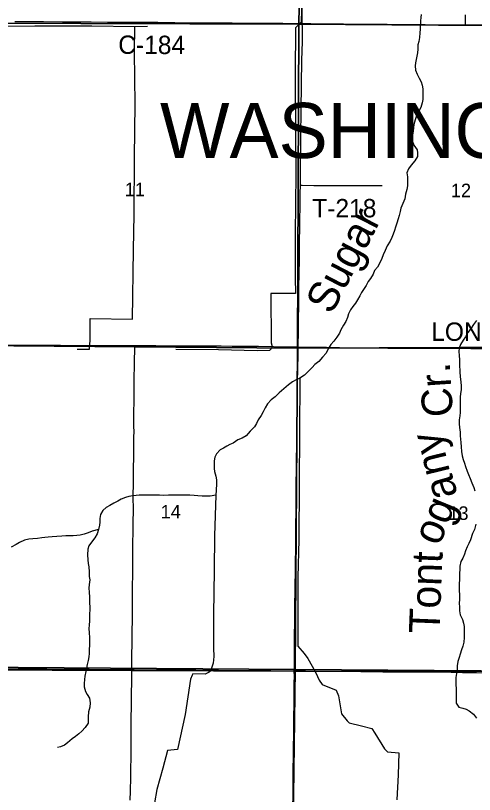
# Model space of a CAD drawing. Extents: x 1443599 to 1910620, y 1028088 to 1361369.
# Drawn here: x 1610745 to 1618246, y 1234297 to 1247021 of the extents above; entities that cross this region are included whole.
import ezdxf

# ---------------------------------------------------------------- set-up
doc = ezdxf.new("R2010")
doc.units = 0
for name, color, linetype in [('GM_X_County_Road', 7, 'Continuous'), ('GM_X_County_Road_Text', 7, 'Continuous'), ('GM_X_Minor_River', 7, 'Continuous'), ('GM_X_Minor_River_Text', 7, 'Continuous'), ('GM_X_Section', 7, 'Continuous'), ('GM_X_Section_Text', 7, 'Continuous'), ('GM_X_State_Route', 7, 'Continuous'), ('GM_X_Township', 7, 'Continuous'), ('GM_X_Township_Road', 7, 'Continuous'), ('GM_X_Township_Road_Text', 7, 'Continuous'), ('GM_X_Township_Text', 7, 'Continuous')]:
    doc.layers.add(name, color=color, linetype=linetype)

msp = doc.modelspace()

# ---------------------------------------------------------------- linework, layer by layer
at = {"layer": 'GM_X_County_Road'}
for points in [[(1610731, 1246926), (1610938, 1246925), (1611099, 1246924), (1611204, 1246924), (1611513, 1246920), (1611703, 1246920), (1611805, 1246919), (1611982, 1246918), (1612248, 1246916), (1612543, 1246914), (1612688, 1246913), (1612954, 1246912), (1613069, 1246911), (1613348, 1246909), (1613942, 1246904), (1614283, 1246902), (1614513, 1246900), (1614723, 1246898), (1614956, 1246896), (1615116, 1246895), (1615304, 1246893), (1615427, 1246892), (1615432, 1246891)], [(1615432, 1246891), (1615570, 1246890), (1615783, 1246887), (1615928, 1246886), (1616105, 1246884), (1616299, 1246883), (1616561, 1246882), (1616686, 1246881), (1616817, 1246880), (1617034, 1246877), (1617175, 1246875), (1617257, 1246875), (1617441, 1246873), (1617608, 1246871), (1617766, 1246870), (1617927, 1246869), (1618084, 1246870), (1618098, 1246869)], [(1618098, 1246869), (1618291, 1246869), (1618596, 1246868), (1618843, 1246867), (1618951, 1246866), (1619036, 1246866), (1619145, 1246866), (1619230, 1246866), (1619338, 1246865), (1619393, 1246865), (1619473, 1246865), (1619614, 1246864), (1619834, 1246863), (1619913, 1246863), (1620001, 1246863), (1620110, 1246862), (1620225, 1246861), (1620389, 1246860), (1620513, 1246859), (1620589, 1246859), (1620665, 1246859), (1620750, 1246859), (1620771, 1246859)]]:
    msp.add_lwpolyline(points, dxfattribs=at)
at = {"layer": 'GM_X_Minor_River'}
for points in [[(1615422, 1247329), (1615413, 1246916), (1615323, 1246819), (1615316, 1246074), (1615319, 1245088), (1615327, 1244437), (1615316, 1243457), (1615318, 1242736), (1615321, 1242483), (1614920, 1242479), (1614923, 1241672), (1614939, 1241615), (1614923, 1241574), (1614894, 1241549), (1614694, 1241546), (1614061, 1241561), (1613365, 1241567)], [(1617375, 1247038), (1617371, 1246988), (1617363, 1246934), (1617358, 1246800), (1617352, 1246740), (1617349, 1246665), (1617337, 1246598), (1617323, 1246544), (1617320, 1246472), (1617314, 1246410), (1617306, 1246356), (1617294, 1246302), (1617282, 1246250), (1617276, 1246198), (1617284, 1246130), (1617308, 1246062), (1617343, 1245997), (1617377, 1245939), (1617393, 1245887), (1617401, 1245824), (1617401, 1245774), (1617403, 1245713), (1617401, 1245649), (1617393, 1245597), (1617370, 1245522), (1617331, 1245447), (1617301, 1245382), (1617279, 1245318), (1617256, 1245243), (1617250, 1245189), (1617244, 1245131)], [(1612901, 1246843), (1612692, 1246837), (1611992, 1246847), (1611059, 1246846), (1609988, 1246840)], [(1611752, 1241572), (1611953, 1241572), (1611964, 1241718), (1611965, 1241979), (1611963, 1242074), (1612654, 1242060), (1612675, 1243194), (1612686, 1243774), (1612687, 1244706), (1612699, 1245573), (1612691, 1246423), (1612692, 1246837)], [(1617244, 1245131), (1617236, 1245069), (1617236, 1245013), (1617236, 1244962), (1617254, 1244906), (1617309, 1244827), (1617317, 1244777), (1617315, 1244717), (1617271, 1244648), (1617212, 1244580), (1617166, 1244517), (1617143, 1244452), (1617153, 1244387), (1617152, 1244311), (1617152, 1244241), (1617141, 1244181), (1617121, 1244103), (1617108, 1244027), (1617042, 1243873), (1617032, 1243821), (1617016, 1243756), (1617000, 1243700), (1616977, 1243628), (1616957, 1243563), (1616939, 1243509), (1616917, 1243448), (1616895, 1243395), (1616866, 1243337), (1616821, 1243259), (1616787, 1243182), (1616754, 1243111), (1616730, 1243053), (1616697, 1242984), (1616659, 1242911), (1616612, 1242855), (1616588, 1242799), (1616546, 1242727), (1616510, 1242674), (1616475, 1242611), (1616435, 1242546), (1616401, 1242495), (1616371, 1242444), (1616332, 1242377), (1616300, 1242322), (1616260, 1242267), (1616220, 1242214), (1616188, 1242149), (1616170, 1242088), (1616143, 1242023), (1616105, 1241964), (1616062, 1241887), (1616042, 1241833), (1615999, 1241765), (1615945, 1241700), (1615901, 1241648), (1615854, 1241575), (1615824, 1241508), (1615761, 1241438), (1615700, 1241370), (1615638, 1241320), (1615595, 1241270), (1615534, 1241210), (1615466, 1241148), (1615390, 1241096), (1615331, 1241072), (1615273, 1241040), (1615209, 1240989), (1615131, 1240921), (1615056, 1240856), (1614986, 1240794), (1614922, 1240742), (1614865, 1240676), (1614827, 1240611), (1614792, 1240548), (1614760, 1240485), (1614709, 1240415), (1614683, 1240357), (1614651, 1240300), (1614582, 1240229), (1614515, 1240155), (1614450, 1240119), (1614379, 1240092), (1614301, 1240038), (1614250, 1240014), (1614198, 1239986), (1614143, 1239956), (1614092, 1239927), (1614027, 1239860), (1614001, 1239804), (1613991, 1239746), (1613989, 1239694), (1613991, 1239622), (1613997, 1239572), (1614016, 1239494), (1614028, 1239436), (1614030, 1239369), (1614022, 1239265)], [(1618280, 1242038), (1618233, 1241976), (1618191, 1241917), (1618140, 1241841), (1618098, 1241772), (1618062, 1241719), (1618019, 1241648), (1617995, 1241585), (1617993, 1241535), (1617995, 1241466), (1618000, 1241396), (1618002, 1241328), (1618005, 1241195), (1618010, 1241124), (1618025, 1241031), (1618031, 1240971), (1618029, 1240909), (1618018, 1240849), (1618014, 1240787), (1618012, 1240717), (1618013, 1240650), (1618013, 1240600), (1618011, 1240534), (1618007, 1240484), (1617997, 1240416), (1617994, 1240350), (1618002, 1240289), (1618010, 1240215), (1618013, 1240154), (1618020, 1240100), (1618024, 1240048), (1618027, 1239973), (1618032, 1239897), (1618044, 1239826), (1618064, 1239771), (1618086, 1239708), (1618102, 1239653), (1618129, 1239578), (1618151, 1239523), (1618175, 1239456), (1618204, 1239386), (1618238, 1239311), (1618252, 1239258)], [(1615390, 1241096), (1615384, 1240205), (1615382, 1239376), (1615375, 1238458), (1615361, 1237844), (1615359, 1237290), (1615361, 1236720), (1615461, 1236599), (1615524, 1236519), (1615595, 1236390), (1615652, 1236281), (1615706, 1236163), (1615755, 1236095), (1615986, 1235998), (1616023, 1235906), (1616073, 1235615), (1616167, 1235497), (1616200, 1235464), (1616397, 1235416), (1616568, 1235376), (1616619, 1235298), (1616778, 1235043), (1616823, 1234995), (1617011, 1234974), (1616998, 1234617), (1616975, 1234206)], [(1614022, 1239265), (1614019, 1239185), (1613995, 1238523), (1613993, 1237959), (1613981, 1237236), (1613981, 1236686), (1613984, 1236548), (1613974, 1236439), (1613948, 1236360), (1613925, 1236303), (1613901, 1236286), (1613846, 1236263), (1613643, 1236267), (1613631, 1236247), (1613604, 1236180), (1613515, 1235605), (1613392, 1235029), (1613231, 1235013), (1613153, 1234727), (1613056, 1234375), (1613014, 1234160)], [(1614019, 1239185), (1613926, 1239168), (1613860, 1239167), (1613796, 1239171), (1613724, 1239176), (1613662, 1239180), (1613596, 1239185), (1613540, 1239187), (1613468, 1239188), (1613403, 1239188), (1613321, 1239187), (1613243, 1239186), (1613155, 1239183), (1613100, 1239185), (1613012, 1239186), (1612916, 1239186), (1612836, 1239185), (1612768, 1239186), (1612715, 1239182), (1612661, 1239176), (1612594, 1239164), (1612540, 1239150), (1612470, 1239118), (1612419, 1239090), (1612350, 1239053), (1612286, 1239019), (1612225, 1238985), (1612171, 1238937), (1612134, 1238872), (1612120, 1238804), (1612120, 1238746), (1612116, 1238694), (1612103, 1238624), (1612077, 1238553), (1612040, 1238488), (1611986, 1238418), (1611943, 1238357), (1611929, 1238305), (1611922, 1238211), (1611925, 1238131), (1611931, 1238070), (1611941, 1238016), (1611948, 1237931), (1611949, 1237857), (1611959, 1237800), (1611949, 1237728), (1611945, 1237668), (1611948, 1237602), (1611951, 1237521), (1611956, 1237423), (1611958, 1237364), (1611958, 1237314), (1611954, 1237246), (1611952, 1237192), (1611953, 1237128), (1611947, 1237068), (1611945, 1237003), (1611949, 1236943), (1611954, 1236856), (1611954, 1236804), (1611952, 1236754), (1611948, 1236648), (1611948, 1236598), (1611944, 1236546), (1611930, 1236482), (1611916, 1236422), (1611906, 1236362), (1611894, 1236304), (1611877, 1236231), (1611871, 1236173), (1611865, 1236111), (1611867, 1236054), (1611886, 1235979), (1611918, 1235928), (1611956, 1235868), (1611967, 1235794), (1611961, 1235721), (1611936, 1235648), (1611931, 1235562), (1611933, 1235512), (1611931, 1235460), (1611885, 1235389), (1611830, 1235329), (1611777, 1235285), (1611725, 1235244), (1611671, 1235204), (1611595, 1235141), (1611543, 1235101), (1611482, 1235075), (1611432, 1235061)], [(1612103, 1238624), (1611996, 1238600), (1611931, 1238568), (1611866, 1238549), (1611801, 1238533), (1611745, 1238529), (1611685, 1238524), (1611626, 1238520), (1611568, 1238520), (1611500, 1238518), (1611417, 1238512), (1611345, 1238506), (1611279, 1238499), (1611226, 1238493), (1611176, 1238489), (1611105, 1238479), (1611029, 1238472), (1610960, 1238467), (1610890, 1238451), (1610812, 1238410), (1610757, 1238378), (1610673, 1238339)], [(1618270, 1238713), (1618245, 1238626), (1618215, 1238561), (1618183, 1238457), (1618153, 1238398), (1618129, 1238343), (1618100, 1238276), (1618082, 1238224), (1618054, 1238159), (1618022, 1238100), (1618009, 1238026), (1617997, 1237687), (1617997, 1237629), (1618000, 1237558), (1617999, 1237476), (1617995, 1237426), (1617999, 1237352), (1618003, 1237297), (1618012, 1237229), (1618048, 1237155), (1618066, 1237094), (1618078, 1237041), (1618080, 1236989), (1618078, 1236923), (1618077, 1236861), (1618071, 1236783), (1618054, 1236717), (1618036, 1236659), (1618013, 1236588), (1617995, 1236532), (1617977, 1236469), (1617962, 1236395), (1617964, 1236341), (1617954, 1236271), (1617944, 1236205), (1617941, 1236147), (1617943, 1236087), (1617949, 1236028)], [(1617949, 1236028), (1617949, 1235974), (1617947, 1235924), (1617947, 1235851), (1617948, 1235785), (1617990, 1235721), (1618056, 1235707), (1618108, 1235691), (1618159, 1235663), (1618229, 1235608), (1618281, 1235540)]]:
    msp.add_lwpolyline(points, dxfattribs=at)
at = {"layer": 'GM_X_Section'}
for points in [[(1610088, 1252173), (1615474, 1252159), (1615377, 1246880), (1610025, 1246900)], [(1615474, 1252159), (1620802, 1252133), (1620703, 1246841), (1615377, 1246880)], [(1610025, 1246900), (1615377, 1246880), (1615356, 1241586), (1610047, 1241629)], [(1615377, 1246880), (1620703, 1246841), (1620687, 1241607), (1615356, 1241586)], [(1610047, 1241629), (1615356, 1241586), (1615314, 1236336), (1610025, 1236377)], [(1620687, 1241607), (1620682, 1241549), (1620622, 1236297), (1615314, 1236336), (1615356, 1241586)], [(1615314, 1236336), (1615247, 1230987), (1609897, 1231040), (1610025, 1236377)], [(1615314, 1236336), (1620622, 1236297), (1620574, 1230950), (1615247, 1230987)]]:
    msp.add_lwpolyline(points, close=True, dxfattribs=at)
at = {"layer": 'GM_X_State_Route'}
msp.add_lwpolyline([(1615273, 1233687), (1615282, 1234353), (1615284, 1234567), (1615289, 1235059), (1615292, 1235289), (1615295, 1235503), (1615299, 1235831), (1615301, 1235979), (1615301, 1236127), (1615302, 1236226), (1615301, 1236314), (1615303, 1236389), (1615304, 1236633), (1615307, 1236871), (1615310, 1237128), (1615312, 1237332), (1615315, 1237680), (1615319, 1237972), (1615324, 1238422), (1615327, 1238671), (1615330, 1238950), (1615333, 1239308), (1615337, 1239669), (1615343, 1240089), (1615347, 1240395), (1615353, 1240867), (1615355, 1240993), (1615360, 1241289), (1615363, 1241447), (1615364, 1241607), (1615364, 1241608), (1615368, 1241875), (1615371, 1242028), (1615374, 1242320), (1615378, 1242599), (1615381, 1242793), (1615385, 1243043), (1615388, 1243282), (1615392, 1243614), (1615396, 1243975), (1615398, 1244113), (1615400, 1244248), (1615403, 1244480), (1615404, 1244605), (1615407, 1244772), (1615408, 1245002), (1615410, 1245193), (1615412, 1245336), (1615414, 1245475), (1615417, 1245895), (1615426, 1246292), (1615433, 1246591), (1615436, 1246748), (1615436, 1246788), (1615434, 1246834), (1615432, 1246891), (1615429, 1246942), (1615429, 1247014), (1615431, 1247175)], dxfattribs=at)
at = {"layer": 'GM_X_Township'}
for points in [[(1620639, 1236303), (1615310, 1236311), (1612650, 1236324), (1610026, 1236334), (1610024, 1238961), (1610033, 1241610), (1610040, 1246868), (1610040, 1246932), (1610066, 1251850)], [(1604643, 1233717), (1604666, 1234695), (1604695, 1236345), (1607915, 1236331), (1610026, 1236334), (1612650, 1236324), (1615310, 1236311), (1620639, 1236303), (1620594, 1233583)]]:
    msp.add_lwpolyline(points, dxfattribs=at)
at = {"layer": 'GM_X_Township_Road'}
for points in [[(1618098, 1246869), (1618098, 1246878), (1618098, 1247031)], [(1615400, 1244248), (1615431, 1244248), (1615619, 1244247), (1615841, 1244246), (1616015, 1244245), (1616137, 1244245), (1616281, 1244245), (1616427, 1244245), (1616570, 1244245), (1616626, 1244244), (1616712, 1244244), (1616737, 1244244)], [(1610037, 1241641), (1610087, 1241641), (1610169, 1241641), (1610304, 1241640), (1610495, 1241638), (1610938, 1241635), (1611283, 1241634), (1611480, 1241634), (1611907, 1241633), (1612235, 1241631), (1612432, 1241632), (1612693, 1241632)], [(1612645, 1236335), (1612648, 1236529), (1612651, 1236808), (1612654, 1237300), (1612656, 1237448), (1612657, 1237546), (1612659, 1237743), (1612661, 1237841), (1612661, 1237973), (1612663, 1238235), (1612663, 1238251), (1612663, 1238284), (1612661, 1238333), (1612662, 1238382), (1612662, 1238398), (1612663, 1238431), (1612663, 1238447), (1612666, 1238545), (1612666, 1238611), (1612668, 1238676), (1612666, 1238726), (1612667, 1238758), (1612671, 1238922), (1612670, 1239185), (1612673, 1239365), (1612674, 1239579), (1612677, 1239857), (1612680, 1240120), (1612681, 1240235), (1612681, 1240251), (1612680, 1240283), (1612680, 1240381), (1612679, 1240529), (1612682, 1240726), (1612684, 1240890), (1612686, 1241120), (1612687, 1241284), (1612689, 1241415), (1612692, 1241539), (1612693, 1241598), (1612693, 1241632)], [(1612693, 1241632), (1612777, 1241632), (1613040, 1241629), (1613220, 1241627), (1613401, 1241624), (1613696, 1241623), (1613942, 1241623), (1614107, 1241623), (1614287, 1241622), (1614505, 1241620), (1614714, 1241618), (1614960, 1241616), (1615256, 1241611), (1615364, 1241607)], [(1615364, 1241607), (1615419, 1241605), (1615614, 1241605), (1615828, 1241604), (1616254, 1241595), (1616435, 1241592), (1616731, 1241591), (1616807, 1241591), (1616832, 1241590), (1616847, 1241590), (1616942, 1241589), (1616989, 1241589), (1617138, 1241588), (1617335, 1241588), (1617488, 1241587)], [(1617488, 1241587), (1617696, 1241585), (1618189, 1241584), (1618599, 1241584), (1618862, 1241586), (1619010, 1241585), (1619272, 1241587), (1619584, 1241586), (1619994, 1241588), (1620158, 1241588), (1620339, 1241589), (1620536, 1241588), (1620651, 1241585), (1620700, 1241581), (1620716, 1241578), (1620731, 1241572)], [(1610002, 1236356), (1610043, 1236356), (1610404, 1236352), (1610748, 1236350), (1610962, 1236349), (1611257, 1236347), (1611553, 1236344), (1611947, 1236342), (1612324, 1236339), (1612537, 1236337), (1612645, 1236335)], [(1612621, 1234202), (1612623, 1234350), (1612627, 1234580), (1612630, 1234777), (1612632, 1234842), (1612633, 1234924), (1612633, 1235121), (1612637, 1235401), (1612637, 1235532), (1612640, 1235745), (1612641, 1235926), (1612643, 1236156), (1612644, 1236287), (1612645, 1236335)], [(1612645, 1236335), (1612685, 1236335), (1612915, 1236334), (1613194, 1236332), (1613473, 1236332), (1613692, 1236332), (1613810, 1236329), (1613916, 1236326), (1614063, 1236325), (1614391, 1236324), (1614670, 1236321), (1614916, 1236320), (1615162, 1236316), (1615261, 1236314), (1615301, 1236314)], [(1615301, 1236314), (1615390, 1236315), (1615486, 1236314), (1615683, 1236312), (1616093, 1236308), (1616224, 1236308), (1616388, 1236305), (1616569, 1236304), (1616749, 1236302), (1616995, 1236302), (1617324, 1236298), (1617865, 1236294), (1618049, 1236291), (1618277, 1236287), (1618544, 1236283), (1618781, 1236282), (1618988, 1236281), (1619209, 1236280), (1619603, 1236279), (1619882, 1236277), (1620063, 1236277), (1620325, 1236277), (1620634, 1236275)]]:
    msp.add_lwpolyline(points, dxfattribs=at)

# ---------------------------------------------------------------- texts
at = {"layer": 'GM_X_County_Road_Text'}
msp.add_text('C-184', height=300, rotation=359.7246, dxfattribs=at).set_placement((1612423, 1246396))
at = {"layer": 'GM_X_Minor_River_Text'}
for s, height, rotation, p in [('Sugar', 500.3, 62.525, (1615909, 1242120)), ('Cr.', 500.4, 93.6941, (1617898, 1240477)), ('ny', 500.4, 103.6923, (1617849, 1239568)), ('a', 500, 105.6922, (1617976, 1239192)), ('og', 500.3, 67.6975, (1617669, 1238340)), ('Tont', 500.4, 87.6952, (1617673, 1236917))]:
    msp.add_text(s, height=height, rotation=rotation, dxfattribs=at).set_placement(p)
at = {"layer": 'GM_X_Section_Text'}
for s, p in [('11', (1612530, 1244070)), ('12', (1617861, 1244054)), ('14', (1613117, 1238805)), ('13', (1617821, 1238782))]:
    msp.add_text(s, height=221, rotation=0, dxfattribs=at).set_placement(p)
at = {"layer": 'GM_X_Township_Road_Text'}
for s, p in [('T-218', (1615595, 1243725)), ('LONG-JUDSON', (1617539, 1241707))]:
    msp.add_text(s, height=300, rotation=0, dxfattribs=at).set_placement(p)
at = {"layer": 'GM_X_Township_Text'}
msp.add_text('WASHINGTON', height=900, rotation=0, dxfattribs=at).set_placement((1613106, 1244694))

doc.saveas('drawing.dxf')
